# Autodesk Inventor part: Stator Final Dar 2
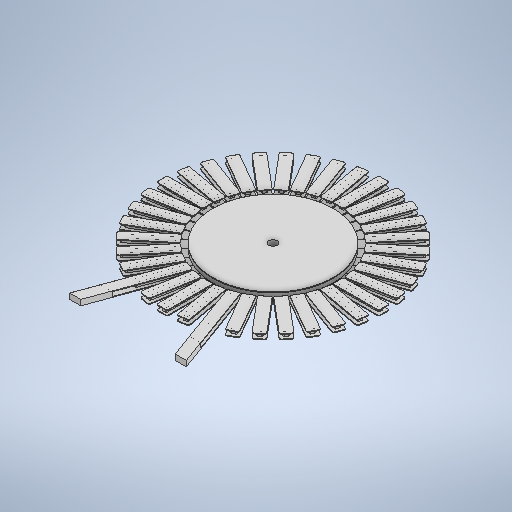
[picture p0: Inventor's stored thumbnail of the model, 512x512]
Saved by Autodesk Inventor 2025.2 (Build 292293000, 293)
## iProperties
Created: 2025-04
Part Number: Stator Final Dar 2
Material: Generic
Document SubType Name: Modeling
Designer: bensa
Density: 1 g/cm^3
Appearance: Default
Author: bensa
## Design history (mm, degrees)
sketch "Sketch1"
  geometry: 1 further point
sketch "Sketch2"
  geometry: L1 (-113.745, 20.056)-(117.255, 20.056); L2 (-108.534, 39.503)-(122.466, 39.503); L3 (-142.1, 32.012)-(-83.012, 21.593); L4 (-83.012, 21.593)-(-85.391, 8.101); L5 (-85.391, 8.101)-(-142.509, 18.173); L6 (-144.132, 20.489)-(-142.447, 30.042); L7 (-142.1, 32.012)-(-85.391, 8.101); L8 (-83.012, 21.593)-(-144.479, 18.52); L9 (-134.382, 56.201)-(-78.001, 35.68); L10 (-78.001, 35.68)-(-82.687, 22.806); L11 (-82.687, 22.806)-(-139.068, 43.327); L12 (-138.384, 45.206)-(-135.066, 54.321); L13 (-134.382, 56.201)-(-82.687, 22.806); L14 (-78.001, 35.68)-(-139.068, 43.327); L15 (144.479, -18.52)-(85.391, -8.101); L16 (85.391, -8.101)-(83.012, -21.593); L17 (83.012, -21.593)-(142.1, -32.012); L18 (142.447, -30.042)-(144.479, -18.52); L19 (144.479, -18.52)-(83.012, -21.593); L20 (85.391, -8.101)-(142.1, -32.012); L21 (137.189, -42.643)-(82.687, -22.806); L22 (82.687, -22.806)-(78.001, -35.68); L23 (78.001, -35.68)-(134.382, -56.201); L24 (135.066, -54.321)-(138.384, -45.206); L25 (139.068, -43.327)-(78.001, -35.68); L26 (82.687, -22.806)-(134.382, -56.201); L27 (-100.026, 57.75)-(130.974, 57.75); L28 (127.7, -65.818)-(77.47, -36.818); L29 (77.47, -36.818)-(70.62, -48.682); L30 (70.62, -48.682)-(120.85, -77.682); L31 (123.582, -76.95)-(129.432, -66.818); L32 (129.432, -66.818)-(70.62, -48.682); L33 (77.47, -36.818)-(122.582, -78.682); L34 (-88.478, 74.242)-(142.522, 74.242); L35 (61.094, -60.206)-(105.524, -97.487); L36 (108.342, -97.241)-(114.577, -89.81); L37 (115.863, -88.278)-(69.9, -49.711); L38 (69.9, -49.711)-(61.094, -60.206); L39 (61.094, -60.206)-(115.863, -88.278); L40 (107.056, -98.773)-(69.9, -49.711); L41 (-74.242, 88.478)-(156.758, 88.478); L42 (49.711, -69.9)-(88.278, -115.863); L43 (89.81, -114.577)-(97.241, -108.342); L44 (98.773, -107.056)-(60.206, -61.094); L45 (60.206, -61.094)-(49.711, -69.9); L46 (49.711, -69.9)-(98.773, -107.056); L47 (88.278, -115.863)-(60.206, -61.094); L48 (-57.75, 100.026)-(173.25, 100.026); L49 (48.682, -70.62)-(78.682, -122.582); L50 (76.95, -123.582)-(68.55, -128.432); L51 (65.818, -127.7)-(36.818, -77.47); L52 (36.818, -77.47)-(48.682, -70.62); L53 (48.682, -70.62)-(66.818, -129.432); L54 (78.682, -122.582)-(36.818, -77.47); L55 (-39.503, 108.534)-(191.497, 108.534); L56 (22.806, -82.687)-(42.643, -137.189); L57 (45.206, -138.384)-(56.201, -134.382); L58 (56.201, -134.382)-(35.68, -78.001); L59 (35.68, -78.001)-(22.806, -82.687); L60 (22.806, -82.687)-(56.201, -134.382); L61 (43.327, -139.068)-(35.68, -78.001); L62 (-20.056, 113.745)-(210.944, 113.745); L63 (8.101, -85.391)-(18.52, -144.479); L64 (20.489, -144.132)-(30.042, -142.447)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; A1 r 2 centre (4.85, -143.5) between (4.85, -145.5) and (6.85, -143.5); A2 r 2 centre (-4.85, -143.5) between (-6.85, -143.5) and (-4.85, -145.5); A3 r 2 centre (20.142, -142.162) between (18.173, -142.509) and (20.489, -144.132); A4 r 2 centre (29.695, -140.478) between (30.042, -142.447) and (31.664, -140.13); A5 r 2 centre (44.522, -136.505) between (42.643, -137.189) and (45.206, -138.384); A6 r 2 centre (53.637, -133.187) between (54.321, -135.066) and (55.517, -132.503); A7 r 2 centre (67.55, -126.7) between (65.818, -127.7) and (68.55, -128.432); A8 r 2 centre (75.95, -121.85) between (76.95, -123.582) and (77.682, -120.85); A9 r 2 centre (88.525, -113.045) between (86.993, -114.33) and (89.81, -114.577); A10 r 2 centre (95.955, -106.81) between (97.241, -108.342) and (97.487, -105.524); A11 r 2 centre (106.81, -95.955) between (105.524, -97.487) and (108.342, -97.241); A12 r 2 centre (113.045, -88.525) between (114.577, -89.81) and (114.33, -86.993); A13 r 2 centre (121.85, -75.95) between (120.85, -77.682) and (123.582, -76.95); A14 r 2 centre (126.7, -67.55) between (128.432, -68.55) and (127.7, -65.818); A15 r 2 centre (133.187, -53.637) between (132.503, -55.517) and (135.066, -54.321); A16 r 2 centre (136.505, -44.522) between (138.384, -45.206) and (137.189, -42.643); A17 r 2 centre (140.478, -29.695) between (140.13, -31.664) and (142.447, -30.042); A18 r 2 centre (142.162, -20.142) between (144.132, -20.489) and (142.509, -18.173); A19 r 2 centre (143.5, -4.85) between (143.5, -6.85) and (145.5, -4.85); A20 r 2 centre (143.5, 4.85) between (145.5, 4.85) and (143.5, 6.85); A21 r 2 centre (142.162, 20.142) between (142.509, 18.173) and (144.132, 20.489); A22 r 2 centre (140.478, 29.695) between (142.447, 30.042) and (140.13, 31.664); A23 r 2 centre (136.505, 44.522) between (137.189, 42.643) and (138.384, 45.206); A24 r 2 centre (133.187, 53.637) between (135.066, 54.321) and (132.503, 55.517); A25 r 2 centre (126.7, 67.55) between (127.7, 65.818) and (128.432, 68.55); A26 r 2 centre (121.85, 75.95) between (123.582, 76.95) and (120.85, 77.682); A27 r 2 centre (113.045, 88.525) between (114.33, 86.993) and (114.577, 89.81); A28 r 2 centre (106.81, 95.955) between (108.342, 97.241) and (105.524, 97.487); A29 r 2 centre (95.955, 106.81) between (97.487, 105.524) and (97.241, 108.342); A30 r 2 centre (88.525, 113.045) between (89.81, 114.577) and (86.993, 114.33); A31 r 2 centre (75.95, 121.85) between (77.682, 120.85) and (76.95, 123.582); A32 r 2 centre (67.55, 126.7) between (68.55, 128.432) and (65.818, 127.7); A33 r 2 centre (53.637, 133.187) between (55.517, 132.503) and (54.321, 135.066); A34 r 2 centre (44.522, 136.505) between (45.206, 138.384) and (42.643, 137.189); A35 r 2 centre (29.695, 140.478) between (31.664, 140.13) and (30.042, 142.447); A36 r 2 centre (20.142, 142.162) between (20.489, 144.132) and (18.173, 142.509); A37 r 2 centre (4.85, 143.5) between (6.85, 143.5) and (4.85, 145.5); A38 r 2 centre (-4.85, 143.5) between (-4.85, 145.5) and (-6.85, 143.5); A39 r 2 centre (-20.142, 142.162) between (-18.173, 142.509) and (-20.489, 144.132); A40 r 2 centre (-29.695, 140.478) between (-30.042, 142.447) and (-31.664, 140.13); A41 r 2 centre (-44.522, 136.505) between (-42.643, 137.189) and (-45.206, 138.384); A42 r 2 centre (-53.637, 133.187) between (-54.321, 135.066) and (-55.517, 132.503); A43 r 2 centre (-67.55, 126.7) between (-65.818, 127.7) and (-68.55, 128.432); A44 r 2 centre (-75.95, 121.85) between (-76.95, 123.582) and (-77.682, 120.85); A45 r 2 centre (-88.525, 113.045) between (-86.993, 114.33) and (-89.81, 114.577); A46 r 2 centre (-95.955, 106.81) between (-97.241, 108.342) and (-97.487, 105.524); A47 r 2 centre (-106.81, 95.955) between (-105.524, 97.487) and (-108.342, 97.241); A48 r 2 centre (-113.045, 88.525) between (-114.577, 89.81) and (-114.33, 86.993); A49 r 2 centre (-121.85, 75.95) between (-120.85, 77.682) and (-123.582, 76.95); A50 r 2 centre (-126.7, 67.55) between (-128.432, 68.55) and (-127.7, 65.818); A51 r 2 centre (-133.187, 53.637) between (-132.503, 55.517) and (-135.066, 54.321); A52 r 2 centre (-136.505, 44.522) between (-138.384, 45.206) and (-137.189, 42.643); A53 r 2 centre (-140.478, 29.695) between (-140.13, 31.664) and (-142.447, 30.042); A54 r 2 centre (-142.162, 20.142) between (-144.132, 20.489) and (-142.509, 18.173); A55 r 2 centre (-143.5, 4.85) between (-143.5, 6.85) and (-145.5, 4.85); A56 r 2 centre (-143.5, -4.85) between (-145.5, -4.85) and (-143.5, -6.85); A57 r 2 centre (-142.162, -20.142) between (-142.509, -18.173) and (-144.132, -20.489); A58 r 2 centre (-140.478, -29.695) between (-142.447, -30.042) and (-140.13, -31.664); A59 r 2 centre (-136.505, -44.522) between (-137.189, -42.643) and (-138.384, -45.206); A60 r 2 centre (-133.187, -53.637) between (-135.066, -54.321) and (-132.503, -55.517); A61 r 2 centre (-126.7, -67.55) between (-127.7, -65.818) and (-128.432, -68.55); A62 r 2 centre (-121.85, -75.95) between (-123.582, -76.95) and (-120.85, -77.682); A63 r 2 centre (-113.045, -88.525) between (-114.33, -86.993) and (-114.577, -89.81); A64 r 2 centre (-106.81, -95.955) between (-108.342, -97.241) and (-105.524, -97.487)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; 119 further points
  constraints: 612 end point, 144 point on circle, 144 tangent, 138 point on line, 110 parallel, 72 centre point, 58 equal radius, 58 perpendicular, 28 midpoint, 15 horizontal, 13 collinear
  dimensions: "d6" = 60 distance of L3.start L3.end; "d7" = 13.7 distance of L3.end L4.end; "d8" = 60 distance of L9.start L9.end; "d9" = 13.7 distance of L9.end L10.end; "d10" = 60 distance of L15.start L15.end; "d11" = 13.7 distance of L16.end L15.end; "d12" = 60 distance of L25.start L21.end; "d13" = 13.7 distance of L22.end L21.end; "d16" = 60 distance of L31.end L28.end; "d17" = 13.7 distance of L29.end L28.end; "d20" = 60 distance of L35.start L40.start; "d21" = 13.7 distance of L37.start L40.start; "d24" = 60 distance of L42.start L42.end; "d25" = 13.7 distance of L44.start L42.end; "d28" = 60 distance of L49.start L49.end; "d29" = 13.7 distance of L49.end L53.end; "d32" = 60 distance of L56.start L61.start; "d33" = 13.7 distance of L57.end L61.start; "d36" = 60 distance of L63.start L63.end; "d37" = 13.7 distance of L65.start L63.end; "d39" = 60 distance of L69.start L69.end; "d40" = 13.7 distance of L71.start L69.end; "d43" = 60 distance of L76.start L76.end; "d44" = 13.7 distance of L77.end L76.end; "d47" = 60 distance of L83.start L88.start; "d48" = 13.7 distance of L84.end L88.start; "d51" = 60 distance of L90.start L90.end; "d52" = 13.7 distance of L90.end L92.start; "d55" = 60 distance of L97.start L102.start; "d56" = 13.7 distance of L98.end L102.start; "d58" = 60 distance of L103.start L108.start; "d59" = 13.7 distance of L104.end L108.start; "d61" = 60 distance of L109.start L109.end; "d62" = 13.7 distance of L109.end L113.end; "d65" = 60 distance of L116.start L116.end; "d66" = 13.7 distance of L116.end L118.start; "d69" = 60 distance of L123.start L123.end; "d70" = 13.7 distance of L124.end L123.end; "d72" = 60 distance of L129.start L130.start; "d73" = 13.7 distance of L130.start L131.start; "d74" = 60 distance of L135.start L135.end; "d75" = 13.7 distance of L135.end L139.end; "d76" = 60 distance of L141.start L141.end; "d77" = 13.7 distance of L142.end L141.end; "d78" = 60 distance of L147.start L147.end; "d79" = 13.7 distance of L147.end L148.end; "d80" = 60 distance of L153.start L153.end; "d81" = 13.7 distance of L153.end L154.end; "d82" = 60 distance of L159.start L159.end; "d83" = 13.7 distance of L159.end L160.end; "d84" = 60 distance of L168.end L165.end; "d85" = 13.7 distance of L165.end L166.end; "d86" = 60 distance of L171.start L171.end; "d87" = 13.7 distance of L171.end L172.end; "d88" = 60 distance of L177.start L177.end; "d89" = 13.7 distance of L177.end L178.end; "d90" = 60 distance of L187.start L183.end; "d91" = 13.7 distance of L183.end L184.end; "d92" = 60 distance of L189.start L189.end; "d93" = 13.7 distance of L189.end L190.end; "d94" = 60 distance of L198.end L195.end; "d95" = 13.7 distance of L196.end L195.end; "d96" = 60 distance of L201.start L201.end; "d97" = 13.7 distance of L202.end L201.end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
extrude "Extrusion2" new body sketch "Sketch2" distance "d126" = 1; taper "d127" = 0 deg
sketch "Sketch3"
  geometry: L1 (-3, 90.35)-(-3, 140.65); L2 (-2, 141.65)-(2, 141.65); L3 (3, 140.65)-(3, 90.35); L4 (2, 89.35)-(-2, 89.35); L5 (-3, 89.35)-(3, 141.65); L6 (-3, 141.65)-(3, 89.35); L7 (12.735, 89.498)-(21.643, 140.019); L8 (22.747, 139.824)-(26.567, 139.151); L9 (17.485, 87.645)-(13.546, 88.34); L10 (12.561, 88.514)-(27.552, 138.977); L11 (21.575, 138.9)-(18.47, 87.472); L12 (-18.644, 88.456)-(-27.378, 137.992); L13 (-26.567, 139.151)-(-22.628, 139.845); L14 (-21.469, 139.034)-(-12.735, 89.498); L15 (-13.546, 88.34)-(-17.485, 87.645); L16 (-18.47, 87.472)-(-21.643, 140.019); L17 (-27.552, 138.977)-(-12.561, 88.514); L18 (-50.924, 131.142)-(-33.721, 83.875); L19 (-32.439, 83.277)-(-28.68, 84.646); L20 (-28.082, 85.927)-(-45.286, 133.194); L21 (-46.568, 133.792)-(-50.327, 132.423); L22 (-51.266, 132.081)-(-27.74, 84.988); L23 (-33.379, 82.935)-(-45.628, 134.134); L24 (-47.613, 76.815)-(-73.063, 120.201); L25 (-72.706, 121.57)-(-69.256, 123.594); L26 (-67.887, 123.237)-(-42.437, 79.851); L27 (-42.794, 78.482)-(-46.244, 76.458); L28 (-47.107, 75.952)-(-68.393, 124.1); L29 (-73.569, 121.064)-(-41.931, 78.988); L30 (-60.374, 67.284)-(-92.706, 105.816); L31 (-92.583, 107.225)-(-89.519, 109.796); L32 (-88.11, 109.673)-(-55.778, 71.14); L33 (-55.901, 69.732)-(-58.965, 67.16); L34 (-59.731, 66.518)-(-88.753, 110.439); L35 (-93.349, 106.582)-(-55.135, 70.374); L36 (-59.731, 66.518)-(-9.431, 66.518); L37 (-71.14, 55.778)-(-109.673, 88.11); L38 (-109.796, 89.519)-(-107.225, 92.583); L39 (-105.816, 92.706)-(-67.284, 60.374); L40 (-67.16, 58.965)-(-69.732, 55.901); L41 (-70.374, 55.135)-(-106.582, 93.349); L42 (-110.439, 88.753)-(-66.518, 59.731); L43 (-70.374, 55.135)-(-20.074, 55.135); L44 (-76.745, 47.773)-(-120.306, 72.923); L45 (-121.672, 72.557)-(-123.672, 69.093); L46 (-123.306, 67.727)-(-79.745, 42.577); L47 (-78.379, 42.943)-(-76.379, 46.407); L48 (-75.879, 47.273)-(-124.172, 68.227); L49 (-121.172, 73.423)-(-78.879, 42.077); L50 (-85.927, 28.082)-(-133.194, 45.286); L51 (-133.792, 46.568)-(-132.423, 50.327); L52 (-131.142, 50.924)-(-83.875, 33.721); L53 (-83.277, 32.439)-(-84.646, 28.68); L54 (-84.988, 27.74)-(-132.081, 51.266); L55 (-134.134, 45.628)-(-82.935, 33.379); L56 (-88.456, 18.644)-(-137.992, 27.378); L57 (-139.151, 26.567)-(-139.845, 22.628); L58 (-139.034, 21.469)-(-89.498, 12.735); L59 (-88.34, 13.546)-(-87.645, 17.485); L60 (-87.472, 18.47)-(-140.019, 21.643); L61 (-138.977, 27.552)-(-88.514, 12.561); L62 (-140.65, -3)-(-90.35, -3); L63 (-89.35, -2)-(-89.35, 2); L64 (-90.35, 3)-(-140.65, 3)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; A1 r 1 centre (-2, 90.35) between (-3, 90.35) and (-2, 89.35); A2 r 1 centre (2, 90.35) between (2, 89.35) and (3, 90.35); A3 r 1 centre (-2, 140.65) between (-2, 141.65) and (-3, 140.65); A4 r 1 centre (2, 140.65) between (3, 140.65) and (2, 141.65); A5 r 1 centre (13.719, 89.325) between (12.735, 89.498) and (13.546, 88.34); A6 r 1 centre (-26.393, 138.166) between (-26.567, 139.151) and (-27.378, 137.992); A7 r 1 centre (-22.454, 138.861) between (-21.469, 139.034) and (-22.628, 139.845); A8 r 1 centre (-13.719, 89.325) between (-13.546, 88.34) and (-12.735, 89.498); A9 r 1 centre (-17.659, 88.63) between (-18.644, 88.456) and (-17.485, 87.645); A10 r 1 centre (-46.226, 132.852) between (-45.286, 133.194) and (-46.568, 133.792); A11 r 1 centre (-49.985, 131.484) between (-50.327, 132.423) and (-50.924, 131.142); A12 r 1 centre (-32.781, 84.217) between (-33.721, 83.875) and (-32.439, 83.277); A13 r 1 centre (-29.022, 85.585) between (-28.68, 84.646) and (-28.082, 85.927); A14 r 1 centre (-68.75, 122.731) between (-67.887, 123.237) and (-69.256, 123.594); A15 r 1 centre (-43.3, 79.345) between (-42.794, 78.482) and (-42.437, 79.851); A16 r 1 centre (-72.2, 120.707) between (-72.706, 121.57) and (-73.063, 120.201); A17 r 1 centre (-46.75, 77.321) between (-47.613, 76.815) and (-46.244, 76.458); A18 r 1 centre (-88.876, 109.03) between (-88.11, 109.673) and (-89.519, 109.796); A19 r 1 centre (-56.544, 70.498) between (-55.901, 69.732) and (-55.778, 71.14); A20 r 1 centre (-91.94, 106.459) between (-92.583, 107.225) and (-92.706, 105.816); A21 r 1 centre (-106.459, 91.94) between (-105.816, 92.706) and (-107.225, 92.583); A22 r 1 centre (-109.03, 88.876) between (-109.796, 89.519) and (-109.673, 88.11); A23 r 1 centre (-59.608, 67.927) between (-60.374, 67.284) and (-58.965, 67.16); A24 r 1 centre (-67.927, 59.608) between (-67.16, 58.965) and (-67.284, 60.374); A25 r 1 centre (-70.498, 56.544) between (-71.14, 55.778) and (-69.732, 55.901); A26 r 1 centre (-122.806, 68.593) between (-123.672, 69.093) and (-123.306, 67.727); A27 r 1 centre (-120.806, 72.057) between (-120.306, 72.923) and (-121.672, 72.557); A28 r 1 centre (-77.245, 46.907) between (-76.379, 46.407) and (-76.745, 47.773); A29 r 1 centre (-79.245, 43.443) between (-79.745, 42.577) and (-78.379, 42.943); A30 r 1 centre (-131.484, 49.985) between (-131.142, 50.924) and (-132.423, 50.327); A31 r 1 centre (-84.217, 32.781) between (-83.277, 32.439) and (-83.875, 33.721); A32 r 1 centre (-85.585, 29.022) between (-85.927, 28.082) and (-84.646, 28.68); A33 r 1 centre (-132.852, 46.226) between (-133.792, 46.568) and (-133.194, 45.286); A34 r 1 centre (-138.166, 26.393) between (-137.992, 27.378) and (-139.151, 26.567); A35 r 1 centre (-138.861, 22.454) between (-139.845, 22.628) and (-139.034, 21.469); A36 r 1 centre (-89.325, 13.719) between (-89.498, 12.735) and (-88.34, 13.546); A37 r 1 centre (-88.63, 17.659) between (-87.645, 17.485) and (-88.456, 18.644); A38 r 1 centre (-140.65, 2) between (-140.65, 3) and (-141.65, 2); A39 r 1 centre (-90.35, 2) between (-89.35, 2) and (-90.35, 3); A40 r 1 centre (-90.35, -2) between (-90.35, -3) and (-89.35, -2); A41 r 1 centre (-140.65, -2) between (-141.65, -2) and (-140.65, -3); A42 r 1 centre (-138.861, -22.454) between (-139.034, -21.469) and (-139.845, -22.628); A43 r 1 centre (-138.166, -26.393) between (-139.151, -26.567) and (-137.992, -27.378); A44 r 1 centre (-88.63, -17.659) between (-88.456, -18.644) and (-87.645, -17.485); A45 r 1 centre (-89.325, -13.719) between (-88.34, -13.546) and (-89.498, -12.735); A46 r 1 centre (-85.585, -29.022) between (-84.646, -28.68) and (-85.927, -28.082); A47 r 1 centre (-84.217, -32.781) between (-83.875, -33.721) and (-83.277, -32.439); A48 r 1 centre (-131.484, -49.985) between (-132.423, -50.327) and (-131.142, -50.924); A49 r 1 centre (-132.852, -46.226) between (-133.194, -45.286) and (-133.792, -46.568); A50 r 1 centre (-122.806, -68.593) between (-123.306, -67.727) and (-123.672, -69.093); A51 r 1 centre (-120.806, -72.057) between (-121.672, -72.557) and (-120.306, -72.923); A52 r 1 centre (-77.245, -46.907) between (-76.745, -47.773) and (-76.379, -46.407); A53 r 1 centre (-79.245, -43.443) between (-78.379, -42.943) and (-79.745, -42.577); A54 r 1 centre (-70.498, -56.544) between (-69.732, -55.901) and (-71.14, -55.778); A55 r 1 centre (-67.927, -59.608) between (-67.284, -60.374) and (-67.16, -58.965); A56 r 1 centre (-106.459, -91.94) between (-107.225, -92.583) and (-105.816, -92.706); A57 r 1 centre (-109.03, -88.876) between (-109.673, -88.11) and (-109.796, -89.519); A58 r 1 centre (-59.608, -67.927) between (-58.965, -67.16) and (-60.374, -67.284); A59 r 1 centre (-56.544, -70.498) between (-55.778, -71.14) and (-55.901, -69.732); A60 r 1 centre (-88.876, -109.03) between (-89.519, -109.796) and (-88.11, -109.673); A61 r 1 centre (-91.94, -106.459) between (-92.706, -105.816) and (-92.583, -107.225); A62 r 1 centre (-46.75, -77.321) between (-46.244, -76.458) and (-47.613, -76.815); A63 r 1 centre (-43.3, -79.345) between (-42.437, -79.851) and (-42.794, -78.482); A64 r 1 centre (-32.781, -84.217) between (-32.439, -83.277) and (-33.721, -83.875)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; 41 further points
  constraints: 460 end point, 287 point on line, 282 point on circle, 218 tangent, 141 centre point, 92 equal radius, 71 midpoint, 55 parallel, 29 perpendicular, 11 horizontal, 10 equal length, 1 vertical
  dimensions: "d129" = 6 distance of L6.start L5.end; "d131" = 52.3 distance of L10.start L7.end; "d132" = 6 distance of L7.end L10.end; "d133" = 1 radius of A1 (derived); "d134" = 52.3 distance of L16.start L17.start; "d135" = 6 distance of L17.start L16.end; "d136" = 1 radius of A6; "d137" = 52.3 distance of L22.start L23.start; "d138" = 6 distance of L22.end L23.start; "d139" = 1 radius of A10 (derived); "d140" = 52.3 distance of L28.start L29.start; "d141" = 6 distance of L29.start L28.end; "d142" = 52.3 distance of L34.start L35.start; "d143" = 130 deg angle of L36 L30; "d144" = 6 distance of L35.start L34.end; "d145" = 52.3 distance of L41.start L42.start; "d146" = 140 deg angle of L43 L37 (derived); "d147" = 6 distance of L42.start L41.end; "d148" = 52.3 distance of L48.start L49.start; "d149" = 6 distance of L48.end L49.start; "d150" = 52.3 distance of L54.start L55.start; "d151" = 6 distance of L55.start L54.end; "d152" = 52.3 distance of L60.start L61.start; "d153" = 6 distance of L60.end L61.start; "d154" = 52.3 distance of L66.start L67.start; "d155" = 6 distance of L66.end L67.start; "d156" = 52.3 distance of L72.start L73.start; "d157" = 6 distance of L73.start L72.end; "d158" = 52.3 distance of L78.start L79.start; "d159" = 20 deg angle of L80 L74; "d160" = 6 distance of L78.end L79.start; "d161" = 52.3 distance of L85.start L86.start; "d162" = 30 deg angle of L87 L81; "d163" = 6 distance of L85.end L86.start; "d164" = 52.3 distance of L92.start L93.start; "d165" = 6 distance of L92.end L93.start; "d166" = 52.3 distance of L98.start L99.start; "d167" = 6 distance of L98.end L99.start; "d168" = 52.3 distance of L104.start L105.start; "d169" = 6 distance of L104.end L105.start; "d170" = 52.3 distance of L110.start L111.start; "d171" = 6 distance of L111.start L110.end; "d172" = 52.3 distance of L116.start L117.start; "d173" = 6 distance of L117.start L116.end; "d174" = 1 radius of A14 (derived); "d175" = 1 radius of A34 (derived); "d176" = 1 radius of A38 (derived); "d177" = 1 radius of A42 (derived); "d178" = 1 radius of A50 (derived); "d179" = 1 radius of A54 (derived); "d180" = 1 radius of A58 (derived); "d181" = 1 radius of A66 (derived); "d182" = 1 radius of A68 (derived); "d183" = 52.3 distance of L172.start L173.start; "d184" = 6 distance of L172.end L173.start; "d185" = 1 radius of A106 (derived); "d186" = 52.3 distance of L178.start L179.start; "d187" = 6 distance of L179.start L178.end; "d188" = 52.3 distance of L184.start L185.start; "d189" = 60 deg angle of L186 L180; "d190" = 6 distance of L185.start L184.end; "d191" = 52.3 distance of L191.start L192.start; "d192" = 50 deg angle of L193 L187; "d193" = 6 distance of L192.start L191.end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
fillet "Fillet1" dims "d225" = 2
fillet "Fillet2" dims "d226" = 2
sketch "Sketch4"
  geometry: L1 (-85.5, -6.85)-(-85.5, 6.85) reference; L2 (85.5, 6.85)-(85.5, -6.85) reference; L3 (-85.5, 6.85)-(85.5, 6.85); L4 (85.5, 6.85)-(85.5, -6.85); L5 (85.5, -6.85)-(-85.5, -6.85); L6 (-85.5, -6.85)-(-85.5, 6.85); L7 (-83.012, -21.593)-(-85.391, -8.101) reference; L8 (-83.012, -21.593)-(-85.391, -8.101); L9 (-85.391, -8.101)-(83.012, 21.593); L10 (83.012, 21.593)-(85.391, 8.101); L11 (85.391, 8.101)-(-83.012, -21.593); L12 (21.593, -83.012)-(8.101, -85.391) reference; L13 (8.101, -85.391)-(21.593, -83.012); L14 (21.593, -83.012)-(-8.101, 85.391); L15 (-8.101, 85.391)-(-21.593, 83.012); L16 (-21.593, 83.012)-(8.101, -85.391); L17 (35.68, -78.001)-(22.806, -82.687) reference; L18 (22.806, -82.687)-(35.68, -78.001); L19 (35.68, -78.001)-(-22.806, 82.687); L20 (-22.806, 82.687)-(-35.68, 78.001); L21 (-35.68, 78.001)-(22.806, -82.687); L22 (48.682, -70.62)-(36.818, -77.47) reference; L23 (36.818, -77.47)-(48.682, -70.62); L24 (48.682, -70.62)-(-36.818, 77.47); L25 (-36.818, 77.47)-(-48.682, 70.62); L26 (-48.682, 70.62)-(36.818, -77.47); L27 (60.206, -61.094)-(49.711, -69.9) reference; L28 (49.711, -69.9)-(60.206, -61.094); L29 (60.206, -61.094)-(-49.711, 69.9); L30 (-49.711, 69.9)-(-60.206, 61.094); L31 (-60.206, 61.094)-(49.711, -69.9); L32 (69.9, -49.711)-(61.094, -60.206) reference; L33 (61.094, -60.206)-(69.9, -49.711); L34 (69.9, -49.711)-(-61.094, 60.206); L35 (-61.094, 60.206)-(-69.9, 49.711); L36 (-69.9, 49.711)-(61.094, -60.206); L37 (77.47, -36.818)-(70.62, -48.682) reference; L38 (70.62, -48.682)-(77.47, -36.818); L39 (77.47, -36.818)-(-70.62, 48.682); L40 (-70.62, 48.682)-(-77.47, 36.818); L41 (-77.47, 36.818)-(70.62, -48.682); L42 (82.687, -22.806)-(78.001, -35.68) reference; L43 (78.001, -35.68)-(82.687, -22.806); L44 (82.687, -22.806)-(-78.001, 35.68); L45 (-78.001, 35.68)-(-82.687, 22.806); L46 (-82.687, 22.806)-(78.001, -35.68); L47 (85.391, -8.101)-(83.012, -21.593) reference; L48 (83.012, -21.593)-(85.391, -8.101); L49 (85.391, -8.101)-(-83.012, 21.593); L50 (-83.012, 21.593)-(-85.391, 8.101); L51 (-85.391, 8.101)-(83.012, -21.593); L52 (8.101, 85.391)-(21.593, 83.012) reference; L53 (8.101, 85.391)-(21.593, 83.012); L54 (21.593, 83.012)-(-8.101, -85.391); L55 (-8.101, -85.391)-(-21.593, -83.012); L56 (-21.593, -83.012)-(8.101, 85.391); L57 (22.806, 82.687)-(35.68, 78.001) reference; L58 (22.806, 82.687)-(35.68, 78.001); L59 (35.68, 78.001)-(-22.806, -82.687); L60 (-22.806, -82.687)-(-35.68, -78.001); L61 (-35.68, -78.001)-(22.806, 82.687); L62 (49.711, 69.9)-(60.206, 61.094) reference; L63 (49.711, 69.9)-(60.206, 61.094); L64 (60.206, 61.094)-(-49.711, -69.9)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; 39 further points
  constraints: 144 end point, 50 equal length, 19 perpendicular, 1 horizontal
  dimensions: "d227" = 171 distance of L7.end L9.end; "d228" = 171 distance of L14.end L12.start; "d229" = 171 distance of L19.end L17.start; "d230" = 171 distance of L24.end L22.start; "d231" = 171 distance of L29.end L27.start; "d232" = 171 distance of L34.end L32.start; "d233" = 171 distance of L39.end L37.start; "d234" = 171 distance of L44.end L42.start; "d235" = 171 distance of L49.end L47.start; "d236" = 171 distance of L52.end L54.end; "d237" = 171 distance of L57.end L59.end; "d238" = 171 distance of L62.end L64.end; "d239" = 171 distance of L67.end L69.end; "d240" = 171 distance of L72.end L73.end; "d241" = 171 distance of L76.end L77.end; "d242" = 171 distance of L83.end L81.start; "d243" = 171 distance of L87.start L89.end
extrude "Extrusion3" join sketch "Sketch4" distance "d244" = 6.25; taper "d246" = 0 deg; dims "d245" = 1, "d247" = 0
sketch "Sketch5"
  geometry: L1 (127.7, 65.818)-(71.231, 33.216) reference; C1 r 86.191 at (0, 0); 2 further points
  constraints: 2 coincident, 1 centre point, 3 other
extrude "Extrusion4" cut sketch "Sketch5" distance "d248" = 6.25; taper "d249" = 0 deg
sketch "Sketch6"
  geometry: L1 (-6.85, 145.5)-(6.85, 145.5); L2 (6.85, 145.5)-(6.85, -145.5); L3 (6.85, -145.5)-(-6.85, -145.5); L4 (-6.85, -145.5)-(-6.85, 145.5); 1 further point
  constraints: 8 end point, 2 parallel, 1 horizontal, 1 perpendicular
  dimensions: "d250" = 291 distance of L1.end L2.end
extrude "Extrusion5" join sketch "Sketch3" distance "d251" = 5.25; taper "d252" = 0 deg
sketch "Sketch7"
  geometry: L1 (18.173, 142.509)-(6.85, 78.296) reference; L2 (30.042, 142.447)-(20.489, 144.132) reference; L3 (18.52, 144.479)-(32.012, 142.1); L4 (32.012, 142.1)-(-18.52, -144.479); L5 (-18.52, -144.479)-(-32.012, -142.1); L6 (-32.012, -142.1)-(18.52, 144.479); L7 (42.643, 137.189)-(20.342, 75.917) reference; L8 (54.321, 135.066)-(45.206, 138.384) reference; L9 (65.818, 127.7)-(33.216, 71.231) reference; L10 (76.95, 123.582)-(68.55, 128.432) reference; L11 (43.327, 139.068)-(56.201, 134.382); L12 (56.201, 134.382)-(-43.327, -139.068); L13 (-43.327, -139.068)-(-56.201, -134.382); L14 (-56.201, -134.382)-(43.327, 139.068); L15 (66.818, 129.432)-(78.682, 122.582); L16 (78.682, 122.582)-(-66.818, -129.432); L17 (-66.818, -129.432)-(-78.682, -122.582); L18 (-78.682, -122.582)-(66.818, 129.432); L19 (86.993, 114.33)-(45.08, 64.381) reference; L20 (97.241, 108.342)-(89.81, 114.577) reference; L21 (88.278, 115.863)-(98.773, 107.056); L22 (98.773, 107.056)-(-88.278, -115.863); L23 (-88.278, -115.863)-(-98.773, -107.056); L24 (-98.773, -107.056)-(88.278, 115.863); L25 (105.524, 97.487)-(55.575, 55.575) reference; L26 (114.577, 89.81)-(108.342, 97.241) reference; L27 (107.056, 98.773)-(115.863, 88.278); L28 (115.863, 88.278)-(-107.056, -98.773); L29 (-107.056, -98.773)-(-115.863, -88.278); L30 (-115.863, -88.278)-(107.056, 98.773); L31 (120.85, 77.682)-(64.381, 45.08) reference; L32 (128.432, 68.55)-(123.582, 76.95) reference; L33 (122.582, 78.682)-(129.432, 66.818); L34 (129.432, 66.818)-(-122.582, -78.682); L35 (-122.582, -78.682)-(-129.432, -66.818); L36 (-129.432, -66.818)-(122.582, 78.682); L37 (132.503, 55.517)-(71.231, 33.216) reference; L38 (138.384, 45.206)-(135.066, 54.321) reference; L39 (134.382, 56.201)-(139.068, 43.327); L40 (139.068, 43.327)-(-134.382, -56.201); L41 (-134.382, -56.201)-(-139.068, -43.327); L42 (-139.068, -43.327)-(134.382, 56.201); L43 (137.189, 42.643)-(75.917, 20.342) reference; L44 (140.13, 31.664)-(75.917, 20.342) reference; L45 (144.132, 20.489)-(142.447, 30.042) reference; L46 (142.1, 32.012)-(144.479, 18.52); L47 (144.479, 18.52)-(-142.1, -32.012); L48 (-142.1, -32.012)-(-144.479, -18.52); L49 (-144.479, -18.52)-(142.1, 32.012); L50 (142.509, 18.173)-(78.296, 6.85) reference; L51 (145.5, -4.85)-(145.5, 4.85) reference; L52 (145.5, 6.85)-(145.5, -6.85); L53 (145.5, -6.85)-(-145.5, -6.85); L54 (-145.5, -6.85)-(-145.5, 6.85); L55 (-145.5, 6.85)-(145.5, 6.85); L56 (142.509, -18.173)-(78.296, -6.85) reference; L57 (142.447, -30.042)-(144.132, -20.489) reference; L58 (144.479, -18.52)-(142.1, -32.012); L59 (142.1, -32.012)-(-144.479, 18.52); L60 (-144.479, 18.52)-(-142.1, 32.012); L61 (-142.1, 32.012)-(144.479, -18.52); L62 (135.066, -54.321)-(138.384, -45.206) reference; L63 (139.091, -43.265)-(134.405, -56.138); L64 (134.405, -56.138)-(-139.045, 43.389)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; 120 further points
  constraints: 136 end point, 34 parallel, 19 perpendicular, 18 point on line, 12 midpoint, 1 other
  dimensions: "d253" = 13.7 distance of L3.start L3.end; "d254" = 291 distance of L3.end L4.end; "d255" = 13.7 distance of L11.start L11.end; "d256" = 291 distance of L11.end L12.end; "d257" = 13.7 distance of L15.start L15.end; "d258" = 291 distance of L15.end L16.end; "d259" = 13.7 distance of L21.start L21.end; "d260" = 291 distance of L21.end L22.end; "d261" = 13.7 distance of L27.start L27.end; "d262" = 291 distance of L27.end L28.end; "d263" = 13.7 distance of L33.start L33.end; "d264" = 291 distance of L33.end L34.end; "d265" = 291 distance of L39.end L40.end; "d266" = 291 distance of L46.end L47.end; "d267" = 13.7 distance of L52.start L52.end; "d268" = 291 distance of L52.end L53.end; "d269" = 291 distance of L58.end L59.end; "d270" = 13.7 distance of L63.start L63.end; "d271" = 291 distance of L63.end L64.end; "d272" = 13.7 distance of L69.start L69.end; "d274" = 13.7 distance of L75.start L75.end; "d275" = 291 distance of L75.end L76.end; "d276" = 13.7 distance of L81.start L81.end; "d277" = 291 distance of L81.end L82.end; "d278" = 13.7 distance of L86.start L86.end; "d279" = 291 distance of L86.end L87.end; "d280" = 13.7 distance of L94.start L94.end; "d281" = 291 distance of L94.end L95.end; "d282" = 291 distance of L98.end L99.end
extrude "Extrusion6" join sketch "Sketch7" distance "d283" = 1; taper "d284" = 0 deg
extrude "Extrusion7" join sketch "Sketch6" distance "d285" = 1; taper "d286" = 0 deg
sketch "Sketch8"
  geometry: C1 r 78.595 at (0, 0); C2 r 85.5 at (0, 0); 1 further point
  constraints: 2 centre point, 2 coincident
  dimensions: "d287" = 157.19 diameter of C1; "d288" = 171 diameter of C2
extrude "Extrusion8" cut sketch "Sketch8" distance "d289" = 1; taper "d290" = 0 deg
fillet "Fillet3" dims "d291" = 2
fillet "Fillet4" dims "d292" = 2
fillet "Fillet5" dims "d293" = 2
fillet "Fillet6" dims "d294" = 2
sketch "Sketch9"
  geometry: L1 (0, 0)-(0, -190); L2 (-36.318, -79.754)-(-23.444, -84.44); L3 (-23.444, -84.44)-(-61.865, -190); L4 (-76.444, -190)-(-36.318, -79.754); L5 (55.517, -132.503)-(36.318, -79.754) reference; L6 (23.444, -84.44)-(36.318, -79.754); L7 (36.318, -79.754)-(76.444, -190); L8 (61.865, -190)-(23.444, -84.44); L9 (-76.444, -190)-(-61.865, -190); L10 (61.865, -190)-(76.444, -190); A1 r 2 centre (-25.323, -83.755) between (-23.444, -84.44) and (-24.744, -81.841) reference; A2 r 2 centre (25.323, -83.755) between (24.744, -81.841) and (23.444, -84.44) reference; 1 further point
  constraints: 19 end point, 2 parallel, 2 perpendicular, 1 vertical
  dimensions: "d295" = 190 distance of L1.start L1.end
extrude "Extrusion9" join sketch "Sketch9" distance "d298" = 1; taper "d299" = 0 deg
sketch "Sketch10"
  geometry: L1 (20.342, 75.917)-(33.216, 71.231); L2 (33.216, 71.231)-(76.444, 190); L3 (61.865, 190)-(20.342, 75.917); L4 (-20.32, 75.926)-(-33.193, 71.238); L5 (-33.193, 71.238)-(-76.445, 190.001); L6 (-61.865, 190.001)-(-20.32, 75.926); L7 (61.865, 190)-(76.444, 190) reference; L8 (76.444, 190)-(61.865, 190); L9 (-61.865, 190.001)-(-76.445, 190.001); A1 r 78.595 centre (0, 0) between (33.216, 71.231) and (20.342, 75.917) reference; 1 further point
  constraints: 16 end point, 2 horizontal, 2 parallel, 2 perpendicular
extrude "Extrusion10" join sketch "Sketch10" distance "d301" = 1; taper "d302" = 0 deg
sketch "Sketch11"
  geometry: L1 (-20.366, -76.053)-(-61.865, -190.001) reference; L2 (-50.939, -160.001)-(-65.52, -160.005); L3 (20.342, -75.917)-(61.865, -190) reference; L4 (76.444, -190)-(33.216, -71.231) reference; L5 (65.525, -160)-(50.946, -160); L6 (-55.579, -132.707)-(-76.445, -190.001) reference; L7 (-65.52, -160.005)-(-76.445, -190.001); L8 (-76.445, -190.001)-(-61.865, -190.001); L9 (-50.939, -160.001)-(-61.865, -190.001); L10 (50.946, -160)-(61.865, -190); L11 (61.865, -190)-(76.444, -190) reference; L12 (76.444, -190)-(65.525, -160); 2 further points
  constraints: 14 end point, 3 collinear, 3 point on line, 2 horizontal, 1 parallel
extrude "Extrusion11" join sketch "Sketch11" distance "d305" = 7.25; taper "d306" = 0 deg
sketch "Sketch12"
  geometry: C1 r 5.5 at (0, 0); 1 further point
  constraints: 1 centre point, 1 coincident
  dimensions: "d307" = 11 diameter of C1
extrude "Extrusion12" cut sketch "Sketch12" distance "d308" = 30; taper "d309" = 0 deg
feature "ᖥ耀ᖧ耀ᖩ耀ᖫ耀ᖭ耀ᖯ耀ᖱ耀ᖳ耀" dims "d6" = 60, "d7" = 13.7, "d8" = 60, "d9" = 13.7, "d10" = 60, "d11" = 13.7, "d12" = 60, "d13" = 13.7, "d16" = 60, "d17" = 13.7, "d20" = 60, "d21" = 13.7, "d24" = 60, "d25" = 13.7, "d28" = 60, "d29" = 13.7, "d32" = 60, "d33" = 13.7, "d36" = 60, "d37" = 13.7, "d39" = 60, "d40" = 13.7, "d43" = 60, "d44" = 13.7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
body "Solid2"
